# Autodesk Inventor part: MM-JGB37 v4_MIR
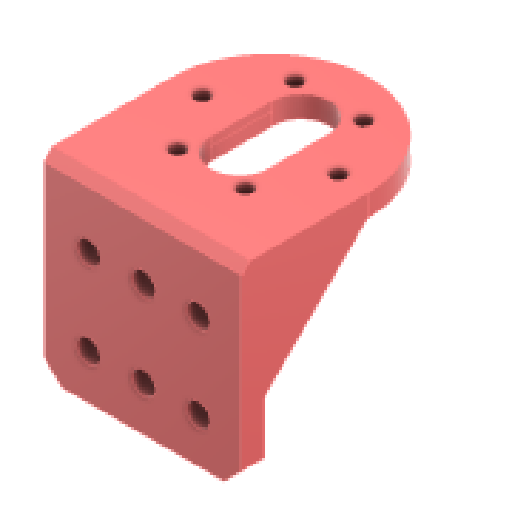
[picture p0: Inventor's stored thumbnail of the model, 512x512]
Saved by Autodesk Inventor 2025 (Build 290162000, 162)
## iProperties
Created: 2024-01
Part Number: MM-JGB37 v4_MIR
Material: Plastica ABS
Document SubType Name: Modeling
Designer: R5800u
Density: 1.06 g/cm^3
Appearance: Liscia - Rosso
Sending System: Autodesk Translation Framework v12.14.0.127
Preprocessor: ST-DEVELOPER v20
Title: MM-JGB37 v4.step
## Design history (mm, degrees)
derived "MM-JGB37 v4.ipt"
  sketch "Schizzo1"
    geometry: L1 (0, -42.5)-(0, 0) reference; L2 (-40, -42.5)-(0, -42.5) reference; L3 (-40, -42.5)-(-40, 0) reference; L4 (0, 0)-(-40, 0) reference; 1 further point
  sketch "Schizzo6"
    geometry: L1 (2.5, -5)-(2.5, 24) reference; L2 (-42.5, 24)-(-42.5, -5) reference; L3 (2.5, -5)-(-42.5, -5) reference; L4 (-42.5, -5)-(-42.5, 0) reference; L5 (-42.5, 0)-(2.5, 0) reference; L6 (2.5, 0)-(2.5, -5) reference; L7 (0, 0)-(-40, 0) reference; L8 (0, -5)-(0, 0) reference; L9 (-40, -5)-(0, -5) reference; L10 (-40, -5)-(-40, 0) reference; 1 further point
  sketch "Schizzo7"
    geometry: L1 (-5, -5)-(-29, -5) reference; L2 (-29, 0)-(-29, -5) reference; L3 (0, 0)-(-29, 0) reference; L4 (0, 0)-(0, -44.5) reference; L5 (-5, -44.5)-(0, -44.5) reference; L6 (-5, -44.5)-(-5, -5) reference; L7 (-27.973, -5.631)-(-5, -28.604) reference; A1 r 1.151 centre (-29, -6.151) between (-27.973, -5.631) and (-29, -5) reference; 1 further point
  sketch "Schizzo8"
    geometry: L1 (-10, -180.5)-(-10, 19.5) reference; L2 (0, 29.5)-(-300, 29.5) reference; L3 (-45, 0)-(0, 0) reference; L4 (-45, 0)-(-45, 15.067) reference; L5 (0, 16.481)-(0, 38.869) reference; L6 (0, 0)-(0, 15.067) reference; 8 further points
  node "Piano di lavoro1"
feature "Solido1::MM-JGB37 v4.ipt" dims "d0" = 10
tag "Lavorazione contrassegno1"
sketch "Schizzo3"
  geometry: L1 (-20, 0)-(-20, 29) reference; L2 (20, 29)-(-20, 29) reference; L3 (20, 29)-(20, 0) reference; L4 (6.5, -7)-(6.5, 7) reference; L5 (-6.5, 7)-(-6.5, -7) reference; C1 r 1.75 at (-15.5, 0) reference; C2 r 1.75 at (7.75, -13.423) reference; C3 r 1.75 at (-7.75, -13.423) reference; C4 r 1.75 at (-7.75, 13.423) reference; C5 r 1.75 at (15.5, 0) reference; C6 r 1.75 at (7.75, 13.423) reference; A1 r 20 centre (0, 0) between (-20, 0) and (20, 0) reference; A2 r 6.5 centre (0, 7) between (6.5, 7) and (-6.5, 7) reference; A3 r 6.5 centre (0, -7) between (-6.5, -7) and (6.5, -7) reference; 1 further point
sketch "Schizzo5"
  geometry: L1 (-20, 0)-(-20, 29) reference; L2 (-20, 29)-(20, 29) reference; L3 (20, 29)-(20, 0) reference; L4 (-6.5, 7)-(-6.5, -7) reference; L5 (6.5, -7)-(6.5, 7) reference; L6 (22.5, 0)-(22.5, 31.5) reference; L7 (22.5, 31.5)-(-22.5, 31.5) reference; L8 (-22.5, 31.5)-(-22.5, 0) reference; L9 (-22.5, 29)-(-20, 29) reference; L10 (22.5, 29)-(20, 29) reference; C1 r 1.75 at (7.75, 13.423) reference; C2 r 1.75 at (15.5, 0) reference; C3 r 1.75 at (-7.75, 13.423) reference; C4 r 1.75 at (-7.75, -13.423) reference; C5 r 1.75 at (7.75, -13.423) reference; C6 r 1.75 at (-15.5, 0) reference; A1 r 20 centre (0, 0) between (-20, 0) and (20, 0) reference; A2 r 6.5 centre (0, -7) between (-6.5, -7) and (6.5, -7) reference; A3 r 6.5 centre (0, 7) between (6.5, 7) and (-6.5, 7) reference; A4 r 22.5 centre (0, 0) between (-22.5, 0) and (22.5, 0) reference; 1 further point
node "Solido1"
